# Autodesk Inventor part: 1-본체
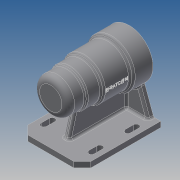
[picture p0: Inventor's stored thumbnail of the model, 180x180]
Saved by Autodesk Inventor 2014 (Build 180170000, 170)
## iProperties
Created: 2017-09
Part Number: 1-본체
Material: Generic
Document SubType Name: Modeling
Designer: kb542-27
Density: 1 g/cm^3
Appearance: Default
Author: kb542-27
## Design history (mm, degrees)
sketch "스케치1"
  geometry: L1 (-56, 0)-(56, 0); L2 (-50, 0)-(-56, 0); L3 (-56, 0)-(-56, 25); L4 (-56, 25)-(-31, 25); L5 (-31, 25)-(-31, 27); L6 (-31, 27)-(-11, 27); L7 (-11, 27)-(-11, 30); L8 (-11, 30)-(28, 30); L9 (28, 30)-(28, 34); L10 (28, 34)-(56, 34); L11 (56, 34)-(56, 21); L12 (56, 21)-(41, 21); L13 (41, 21)-(41, 24); L14 (41, 24)-(-13, 24); L15 (-13, 24)-(-13, 21); L16 (-13, 21)-(-25, 21); L17 (-25, 21)-(-25, 17.5); L18 (-25, 17.5)-(-43, 17.5); L19 (-43, 17.5)-(-43, 16); L20 (-43, 16)-(-47, 16); L21 (-47, 16)-(-47, 10.5); L22 (-47, 10.5)-(-50, 10.5); L23 (-50, 10.5)-(-50, 0); 2 further points
  constraints: 46 end point, 11 parallel, 10 perpendicular, 2 coincident, 2 collinear, 1 horizontal, 1 midpoint, 1 vertical alignment
  dimensions: "d0" = 112 distance between parallel lines of L11 L3; "d1" = 84 distance between parallel lines of L3 L9; "d2" = 45 distance between parallel lines of L3 L7; "d3" = 25 distance between parallel lines of L3 L5; "d4" = 42 diameter of L12 L1; "d5" = 48 diameter of L14 L1; "d6" = 42 diameter of L16 L1; "d7" = 35 diameter of L18 L1; "d8" = 32 diameter of L20 L1; "d9" = 21 diameter of L22 L1; "d10" = 3 distance of L21.end L22.end; "d11" = 4 distance of L19.end L20.end; "d12" = 18 distance of L17.end L18.end; "d13" = 12 distance of L15.end L16.end; "d14" = 54 distance of L13.end L14.end; "d15" = 15 distance of L11.end L12.end; "d16" = 60 diameter of L8 L1; "d17" = 54 diameter of L6 L1; "d18" = 50 diameter of L4 L1; "d19" = 68 diameter of L10 L1
revolve "회전1" sketch "스케치1" stored, may be unused: angle "d20" = 90 deg
node "작업 평면1"
sketch "스케치2"
  geometry: L1 (-56, 34)-(-56, -34) reference; L2 (-56, 45)-(44, 45); L3 (56, 33)-(56, -33); L4 (44, -45)-(-56, -45); L5 (-56, -45)-(-56, 45); L6 (56, 33)-(44, 45); L7 (56, -33)-(44, -45); L8 (-32, 34)-(-20, 34); L9 (-32, 30)-(-20, 30); L10 (-20, 38)-(-32, 38); L11 (20, 34)-(32, 34); L12 (20, 38)-(32, 38); L13 (32, 30)-(20, 30); L14 (0, 0)-(-56, 0); L15 (-32, -30)-(-20, -30); L16 (-20, -38)-(-32, -38); L17 (-32, -34)-(-20, -34); L18 (20, -34)-(32, -34); L19 (20, -38)-(32, -38); L20 (32, -30)-(20, -30); A1 r 4 centre (-32, 34) between (-32, 38) and (-32, 30); A2 r 4 centre (-20, 34) between (-20, 30) and (-20, 38); A3 r 4 centre (20, 34) between (20, 38) and (20, 30); A4 r 4 centre (32, 34) between (32, 30) and (32, 38); A5 r 4 centre (-20, -34) between (-20, -38) and (-20, -30); A6 r 4 centre (-32, -34) between (-32, -30) and (-32, -38); A7 r 4 centre (20, -34) between (20, -30) and (20, -38); A8 r 4 centre (32, -34) between (32, -38) and (32, -30); 6 further points
  constraints: 46 end point, 16 point on circle, 14 symmetric about line, 8 centre point, 8 tangent, 7 parallel, 4 midpoint, 4 point on line, 2 collinear, 1 horizontal, 1 horizontal alignment, 1 perpendicular, 4 other
  dimensions: "d22" = 112 distance of L2.start point (56, 45); "d23" = 90 distance of L4.end L2.start; "d24" = 12 distance of L3.start point (56, 45); "d25" = 12 distance of L2.end point (56, 45) (= d24); "d26" = 12 distance of L3.end point (56, -45) (= d24); "d27" = 12 distance of L4.start point (56, -45) (= d26); "d28" = 12 distance of L8.start L8.end; "d29" = 12 distance of L11.start L11.end; "d30" = 34 vertical distance of L14.start point (-26, 34); "d31" = 24 distance from line of L1 L8.start; "d33" = 4 radius of A2; "d34" = 4 radius of A4; "d35" = 40 distance of L11.start L8.end
extrude "돌출1" join sketch "스케치2" distance "d36" = 8; taper "d37" = 0 deg
sketch "스케치3"
  geometry: L1 (-62, 45)-(-62, -45) reference; L2 (-62, 35)-(-26.008, 21.9); L3 (-26.008, -21.9)-(-62, -35); L4 (-70, 45)-(-62, 45) reference; A1 r 34 centre (0, 0) between (-26.008, 21.9) and (-26.008, -21.9) reference
  constraints: 4 end point, 2 point on circle, 2 point on line
  dimensions: "d38" = 10 distance from line of L4 L2.start; "d39" = 10 distance of L1.end L3.end; "d40" = 110 deg angle of L1 L3; "d41" = 110 deg angle of L1 L2
extrude "돌출2" join sketch "스케치3" distance "d42" = 8; taper "d43" = 0 deg
sketch "스케치4"
  geometry: L1 (-56, -25)-(-56, 25) reference; L2 (-56, 25)-(-31, 25) reference; L3 (-31, 25)-(-31, 27) reference; L4 (-31, 27)-(-11, 27) reference; L5 (-11, 27)-(-11, 30) reference; L6 (-11, 30)-(28, 30) reference; L7 (28, 30)-(28, 34) reference; L8 (28, 34)-(56, 34) reference; L9 (56, 34)-(56, 21) reference; L10 (56, 21)-(41, 21) reference; L11 (41, 21)-(41, 24) reference; L12 (41, 24)-(-13, 24) reference; L13 (-13, 24)-(-13, 21) reference; L14 (-13, 21)-(-25, 21) reference; L15 (-25, 21)-(-25, 17.5) reference; L16 (-25, 17.5)-(-43, 17.5) reference; L17 (-43, 17.5)-(-43, 16) reference; L18 (-43, 16)-(-47, 16) reference; L19 (-47, 16)-(-47, 10.5) reference; L20 (-47, 10.5)-(-50, 10.5) reference; L21 (-50, 10.5)-(-50, -10.5) reference; L22 (-50, -10.5)-(-47, -10.5) reference; L23 (-47, -10.5)-(-47, -16) reference; L24 (-47, -16)-(-43, -16) reference; L25 (-43, -16)-(-43, -17.5) reference; L26 (-43, -17.5)-(-25, -17.5) reference; L27 (-25, -17.5)-(-25, -21) reference; L28 (-25, -21)-(-13, -21) reference; L29 (-13, -21)-(-13, -24) reference; L30 (-13, -24)-(41, -24) reference; L31 (41, -24)-(41, -21) reference; L32 (41, -21)-(56, -21) reference; L33 (56, -21)-(56, -70) reference; L34 (56, -70)-(-56, -70) reference; L35 (-56, -70)-(-56, -62) reference; L36 (-56, -62)-(48, -62) reference; L37 (48, -62)-(48, -34) reference; L38 (48, -34)-(28, -34) reference; L39 (28, -34)-(28, -30) reference; L40 (28, -30)-(-11, -30) reference; L41 (-11, -30)-(-11, -27) reference; L42 (-11, -27)-(-31, -27) reference; L43 (-31, -27)-(-31, -25) reference; L44 (-31, -25)-(-56, -25) reference; L45 (-24.622, -27)-(-34, -62); 1 further point
  constraints: 2 end point, 2 point on line
  dimensions: "d44" = 22 distance from line of L35 L45.end; "d45" = 105 deg angle of L36 L45
feature "리브1" sketch "스케치4" dims "d46" = 1, "d47" = 8, "d48" = 0, "d49" = 0, "d50" = 1, "d51" = 1
node "작업 평면3"
  node "작업 평면2"
sketch "스케치5"
  geometry: L1 (47.5, -26.008)-(47.5, 34) reference; 2 further points
  constraints: 1 horizontal alignment, 1 other
  dimensions: "d53" = 48 distance from line of L1 point (-0.5, 0)
feature "엠보싱1" sketch "스케치5" dims "d0" = 112, "d1" = 84, "d2" = 45, "d3" = 25, "d4" = 42, "d5" = 48, "d6" = 42, "d7" = 35, "d8" = 32, "d9" = 21, "d10" = 3, "d11" = 4, "d12" = 18, "d13" = 12, "d14" = 54, "d15" = 15, "d16" = 60, "d17" = 54, "d18" = 50, "d19" = 68, "d54" = 0.5, "d55" = 0
sketch "스케치6" dims "d56" = 52
  geometry: C1 r 21 at (70, 45) reference; A1 r 34 centre (70, 45) between (43.992, 23.1) and (43.992, 66.9) reference; 2 further points
  constraints: 2 horizontal alignment, 1 coincident, 2 other
hole "구멍1" sketch "스케치6" at (96, 45) diameter "d57" = 3.242; stored, may be unused: countersink angle "d61" = 90 deg, drill point angle "d63" = 118 deg; dims "d58" = 8, "d59" = 4, "d60" = 2, "d62" = 11
fillet "모깎기1" dims "d67" = 3, "d68" = 0.3
fillet "모깎기2" dims "d69" = 9
fillet "모깎기3" dims "d70" = 3
fillet "모깎기4" dims "d71" = 3
fillet "모깎기5" dims "d72" = 3
fillet "모깎기6" dims "d73" = 3
fillet "모깎기7" dims "d74" = 3
fillet "모깎기8" dims "d75" = 3
node "솔리드1"
pattern_circular "원형 패턴1" dims angle "d65" = 360 deg
node "절단 모서리 투영1"
other parameters: "d52" = 0.5
